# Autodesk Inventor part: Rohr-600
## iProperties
Created: 2012-04
Part Number: Rohr-600
Document SubType Name: Modeling
Designer: T.Cybinski
Mass: 4514.85 g
Surface Area: 75292.6 cm^2
Volume: 4514.85 cm^3
Density: 1 g/cm^3
Author: T.Cybinski
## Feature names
1. Umdrehung1 [Revolution]
2. Wandstärke1
